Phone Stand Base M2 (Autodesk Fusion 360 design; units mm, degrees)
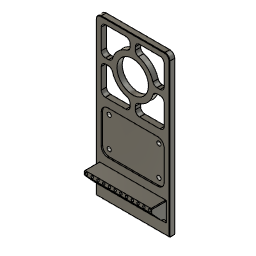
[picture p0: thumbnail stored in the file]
sketch "Sketch1" plane through (0, 0, 0) normal (0, 0, 1) x axis (1, 0, 0)
  line L1 (190.5, 0) -> (0, 0)
  line L2 (190.5, 88.9) -> (190.5, 0)
  line L3 (0, 88.9) -> (190.5, 88.9)
  line L4 (0, 0) -> (0, 88.9)
  point P1 (0, 0)
  point P2 (0, 0)
  point P3 (190.5, 0)
  point P5 (0, 88.9)
  horizontal L1
  vertical L2
  horizontal L3
  vertical L4
  coincident P1 P2
  dimension "d1" distance P2 P3 = 190.5
  dimension "d2" distance P2 P5 = 88.9
extrude "Extrude1" new body sketch "Sketch1" along normal blind 6.35
sketch "Sketch2" plane through (0, 0, 6.35) normal (0, 0, 1) x axis (-1, 0, 0)
  line L1 (0, 0) -> (0, -88.9)
  line L2 (-190.5, 0) -> (0, 0)
  line L3 (-190.5, -88.9) -> (-190.5, 0)
  line L4 (0, -88.9) -> (-190.5, -88.9)
  line L5 (-36.83, -85.09) -> (-19.05, -85.09)
  line L6 (-36.83, -3.81) -> (-36.83, -85.09)
  line L7 (-19.05, -3.81) -> (-36.83, -3.81)
  line L8 (-19.05, -85.09) -> (-19.05, -3.81)
  horizontal L5
  vertical L6
  horizontal L7
  vertical L8
  dimension "d5" distance L1 L8 = 19.05
  dimension "d6" distance L6 L8 = 17.78
  dimension "d7" distance L4 L5 = 3.81
  dimension "d8" distance L2 L7 = 3.81
extrude "Extrude2" add sketch "Sketch2" profile of L5 L6 L7 L8 along normal blind 17.78
fillet "Fillet1" radius 6
chamfer "Chamfer1" distance 12.7 distance 11.43
fillet "Fillet2" radius 6
chamfer "Chamfer2" distance 0.5 distance 0.508
fillet "Fillet4" radius 0.75
sketch "Sketch5" plane through (0, 0, 6.35) normal (0, 0, 1) x axis (-1, 0, 0)
  line L1 (-36.08, -85.09) -> (-13.05, -85.09)
  line L2 (-36.83, -4.56) -> (-36.83, -84.34)
  line L3 (-13.05, -3.81) -> (-36.08, -3.81)
  line L4 (-13.05, -85.09) -> (-13.05, -3.81)
  line L5 (-184.5, -0.5) -> (-0.5, -0.5)
  line L6 (-190, -82.9) -> (-190, -6)
  line L7 (-0.5, -88.4) -> (-184.5, -88.4)
  line L8 (-0.5, -0.5) -> (-0.5, -88.4)
  line L9 (0, -88.9) -> (-184.5, -88.9)
  line L10 (-190.5, -82.9) -> (-190.5, -6)
  line L11 (-184.15, -77.47) -> (-184.15, -52.705)
  line L12 (-154.305, -82.55) -> (-179.07, -82.55)
  line L13 (-184.15, -44.45) -> (-171.45, -44.45)
  line L14 (-190.5, -44.45) -> (-190, -44.45)
  line L15 (-179.07, -47.625) -> (-171.2508, -47.625)
  line L16 (-146.05, -82.55) -> (-146.05, -69.85)
  line L17 (-146.05, -88.9) -> (-146.05, -88.4)
  line L18 (-149.225, -77.47) -> (-149.225, -69.6508)
  line L19 (-149.225, -88.9) -> (-149.225, -88.4)
  arc A1 centre (-36.08, -84.34) radius 0.75 clockwise from (-36.08, -85.09) to (-36.83, -84.34)
  arc A2 centre (-36.08, -4.56) radius 0.75 clockwise from (-36.83, -4.56) to (-36.08, -3.81)
  arc A3 centre (-184.5, -6) radius 5.5 clockwise from (-190, -6) to (-184.5, -0.5)
  arc A4 centre (-184.5, -82.9) radius 5.5 clockwise from (-184.5, -88.4) to (-190, -82.9)
  circle C1 centre (-146.05, -44.45) radius 19.05
  circle C2 centre (-146.05, -44.45) radius 25.4
  arc A5 centre (-179.07, -77.47) radius 5.08 clockwise from (-179.07, -82.55) to (-184.15, -77.47)
  arc A6 centre (-154.305, -77.47) radius 5.08 clockwise from (-149.225, -77.47) to (-154.305, -82.55)
  arc A7 centre (-179.07, -52.705) radius 5.08 clockwise from (-184.15, -52.705) to (-179.07, -47.625)
  point P24 (-149.225, -69.6508)
  point P25 (-146.05, -69.85)
  point P26 (-171.2508, -47.625)
  point P27 (-171.45, -44.45)
  point P28 (-190.5, -44.45)
  point P29 (-184.15, -44.45)
  point P30 (-190, -44.45)
  point P31 (-146.05, -82.55)
  point P32 (-146.05, -88.4)
  point P33 (-149.225, -88.4)
  point P34 (-149.225, -88.9)
  point P35 (-146.05, -88.9)
  point P18 (-146.05, -44.45)
  coincident C2 P24
  coincident C2 P25
  coincident C2 P26
  coincident C2 P27
  coincident L10 P28
  coincident L11 P29
  coincident L6 P30
  collinear L13 L14
  coincident L12 P31
  coincident L7 P32
  collinear L16 L17
  coincident L7 P33
  collinear L18 L19
  coincident L9 P34
  coincident L9 P35
  tangent L12 A5
  tangent L11 A5
  tangent L18 A6
  tangent L12 A6
  tangent L11 A7
  tangent L15 A7
  dimension "d51" distance P18 L9 = 44.45
  dimension "d52" distance P18 L10 = 44.45
  dimension "d53" diameter C1 = 38.1
  dimension "d54" = 6.35
  dimension "d58" radius A5 = 5.08
  dimension "d59" radius A6 = 5.08
  dimension "d60" radius A7 = 5.08
extrude "Extrude5" cut sketch "Sketch5" profile of C1 C2 L19 L15 L11 L12 A5 A6 A7 no distance stored
fillet "Fillet5" radius 5
fillet "Fillet6" radius 5
circular_pattern "C-Pattern1" TotalAngle 360
fillet "Fillet7" radius 5
sketch "Sketch6" plane through (0, 0, 6.35) normal (0, 0, 1) x axis (-1, 0, 0)
  line L1 (-107.95, -77.47) -> (-107.95, -52.705)
  line L2 (-137.795, -82.55) -> (-113.03, -82.55)
  line L3 (-142.875, -73.7302) -> (-142.875, -77.47)
  line L4 (-113.03, -47.625) -> (-116.7698, -47.625)
  line L5 (-113.03, -6.35) -> (-137.795, -6.35)
  line L6 (-107.95, -36.195) -> (-107.95, -11.43)
  line L7 (-116.7698, -41.275) -> (-113.03, -41.275)
  line L8 (-142.875, -11.43) -> (-142.875, -15.1698)
  line L9 (-184.15, -11.43) -> (-184.15, -36.195)
  line L10 (-154.305, -6.35) -> (-179.07, -6.35)
  line L11 (-149.225, -15.1698) -> (-149.225, -11.43)
  line L12 (-179.07, -41.275) -> (-175.3302, -41.275)
  line L13 (-179.07, -82.55) -> (-154.305, -82.55)
  line L14 (-184.15, -52.705) -> (-184.15, -77.47)
  line L15 (-175.3302, -47.625) -> (-179.07, -47.625)
  line L16 (-149.225, -77.47) -> (-149.225, -73.7302)
  line L17 (-36.08, -85.09) -> (-13.05, -85.09)
  line L18 (-36.83, -4.56) -> (-36.83, -84.34)
  line L19 (-13.05, -3.81) -> (-36.08, -3.81)
  line L20 (-13.05, -85.09) -> (-13.05, -3.81)
  line L21 (-184.5, -0.5) -> (-0.5, -0.5)
  line L22 (-190, -82.9) -> (-190, -6)
  line L23 (-0.5, -88.4) -> (-184.5, -88.4)
  line L24 (-0.5, -0.5) -> (-0.5, -88.4)
  line L25 (-46.355, -82.55) -> (-98.425, -82.55)
  line L26 (-46.355, -6.35) -> (-46.355, -82.55)
  line L27 (-98.425, -6.35) -> (-46.355, -6.35)
  line L28 (-98.425, -82.55) -> (-98.425, -6.35)
  line L29 (0, -88.9) -> (-184.5, -88.9)
  arc A1 centre (-113.03, -52.705) radius 5.08 clockwise from (-113.03, -47.625) to (-107.95, -52.705)
  arc A2 centre (-113.03, -77.47) radius 5.08 clockwise from (-107.95, -77.47) to (-113.03, -82.55)
  arc A3 centre (-137.795, -77.47) radius 5.08 clockwise from (-137.795, -82.55) to (-142.875, -77.47)
  arc A4 centre (-137.875, -73.7302) radius 5 clockwise from (-142.875, -73.7302) to (-139.2196, -68.9144)
  arc A5 centre (-146.05, -44.45) radius 25.4 clockwise from (-121.5856, -51.2804) to (-139.2196, -68.9144)
  arc A6 centre (-116.7698, -52.625) radius 5 clockwise from (-121.5856, -51.2804) to (-116.7698, -47.625)
  arc A7 centre (-137.795, -11.43) radius 5.08 clockwise from (-142.875, -11.43) to (-137.795, -6.35)
  arc A8 centre (-113.03, -11.43) radius 5.08 clockwise from (-113.03, -6.35) to (-107.95, -11.43)
  arc A9 centre (-113.03, -36.195) radius 5.08 clockwise from (-107.95, -36.195) to (-113.03, -41.275)
  arc A10 centre (-116.7698, -36.275) radius 5 clockwise from (-116.7698, -41.275) to (-121.5856, -37.6196)
  arc A11 centre (-146.05, -44.45) radius 25.4 clockwise from (-139.2196, -19.9856) to (-121.5856, -37.6196)
  arc A12 centre (-137.875, -15.1698) radius 5 clockwise from (-139.2196, -19.9856) to (-142.875, -15.1698)
  arc A13 centre (-179.07, -36.195) radius 5.08 clockwise from (-179.07, -41.275) to (-184.15, -36.195)
  arc A14 centre (-179.07, -11.43) radius 5.08 clockwise from (-184.15, -11.43) to (-179.07, -6.35)
  arc A15 centre (-154.305, -11.43) radius 5.08 clockwise from (-154.305, -6.35) to (-149.225, -11.43)
  arc A16 centre (-154.225, -15.1698) radius 5 clockwise from (-149.225, -15.1698) to (-152.8804, -19.9856)
  arc A17 centre (-146.05, -44.45) radius 25.4 clockwise from (-170.5144, -37.6196) to (-152.8804, -19.9856)
  arc A18 centre (-175.3302, -36.275) radius 5 clockwise from (-170.5144, -37.6196) to (-175.3302, -41.275)
  arc A19 centre (-154.305, -77.47) radius 5.08 clockwise from (-149.225, -77.47) to (-154.305, -82.55)
  arc A20 centre (-179.07, -77.47) radius 5.08 clockwise from (-179.07, -82.55) to (-184.15, -77.47)
  arc A21 centre (-179.07, -52.705) radius 5.08 clockwise from (-184.15, -52.705) to (-179.07, -47.625)
  arc A22 centre (-175.3302, -52.625) radius 5 clockwise from (-175.3302, -47.625) to (-170.5144, -51.2804)
  arc A23 centre (-146.05, -44.45) radius 25.4 clockwise from (-152.8804, -68.9144) to (-170.5144, -51.2804)
  arc A24 centre (-154.225, -73.7302) radius 5 clockwise from (-152.8804, -68.9144) to (-149.225, -73.7302)
  circle C1 centre (-146.05, -44.45) radius 19.05
  arc A25 centre (-36.08, -84.34) radius 0.75 clockwise from (-36.08, -85.09) to (-36.83, -84.34)
  arc A26 centre (-36.08, -4.56) radius 0.75 clockwise from (-36.83, -4.56) to (-36.08, -3.81)
  arc A27 centre (-184.5, -6) radius 5.5 clockwise from (-190, -6) to (-184.5, -0.5)
  arc A28 centre (-184.5, -82.9) radius 5.5 clockwise from (-184.5, -88.4) to (-190, -82.9)
  horizontal L25
  vertical L26
  horizontal L27
  vertical L28
  dimension "d70" distance L25 L29 = 6.35
  dimension "d71" distance L25 L27 = 76.2
  dimension "d72" distance L6 L28 = 9.525
  dimension "d73" distance L18 L26 = 9.525
extrude "Extrude6" cut sketch "Sketch6" profile of L25 L26 L27 L28 against normal blind 1.6
fillet "Fillet8" radius 8
hole "Hole2" HoleDiameter 5.035 TipAngle 118
hole "Hole3" HoleDiameter 5.035 TipAngle 118
hole "Hole4" HoleDiameter 5.035 TipAngle 118
hole "Hole5" HoleDepth 30.48 HoleDiameter 5.035 TipAngle 118
hole "Hole6" HoleDepth 24.13 HoleDiameter 3 TipAngle 118 RefDim1 2.54 RefDim2 6.35
rectangular_pattern "R-Pattern2" countU 12 uSpaceDistance 76.2 vSpaceDistance 0
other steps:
thread "Thread2"
thread "Thread3"
thread "Thread4"
thread "Thread5"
